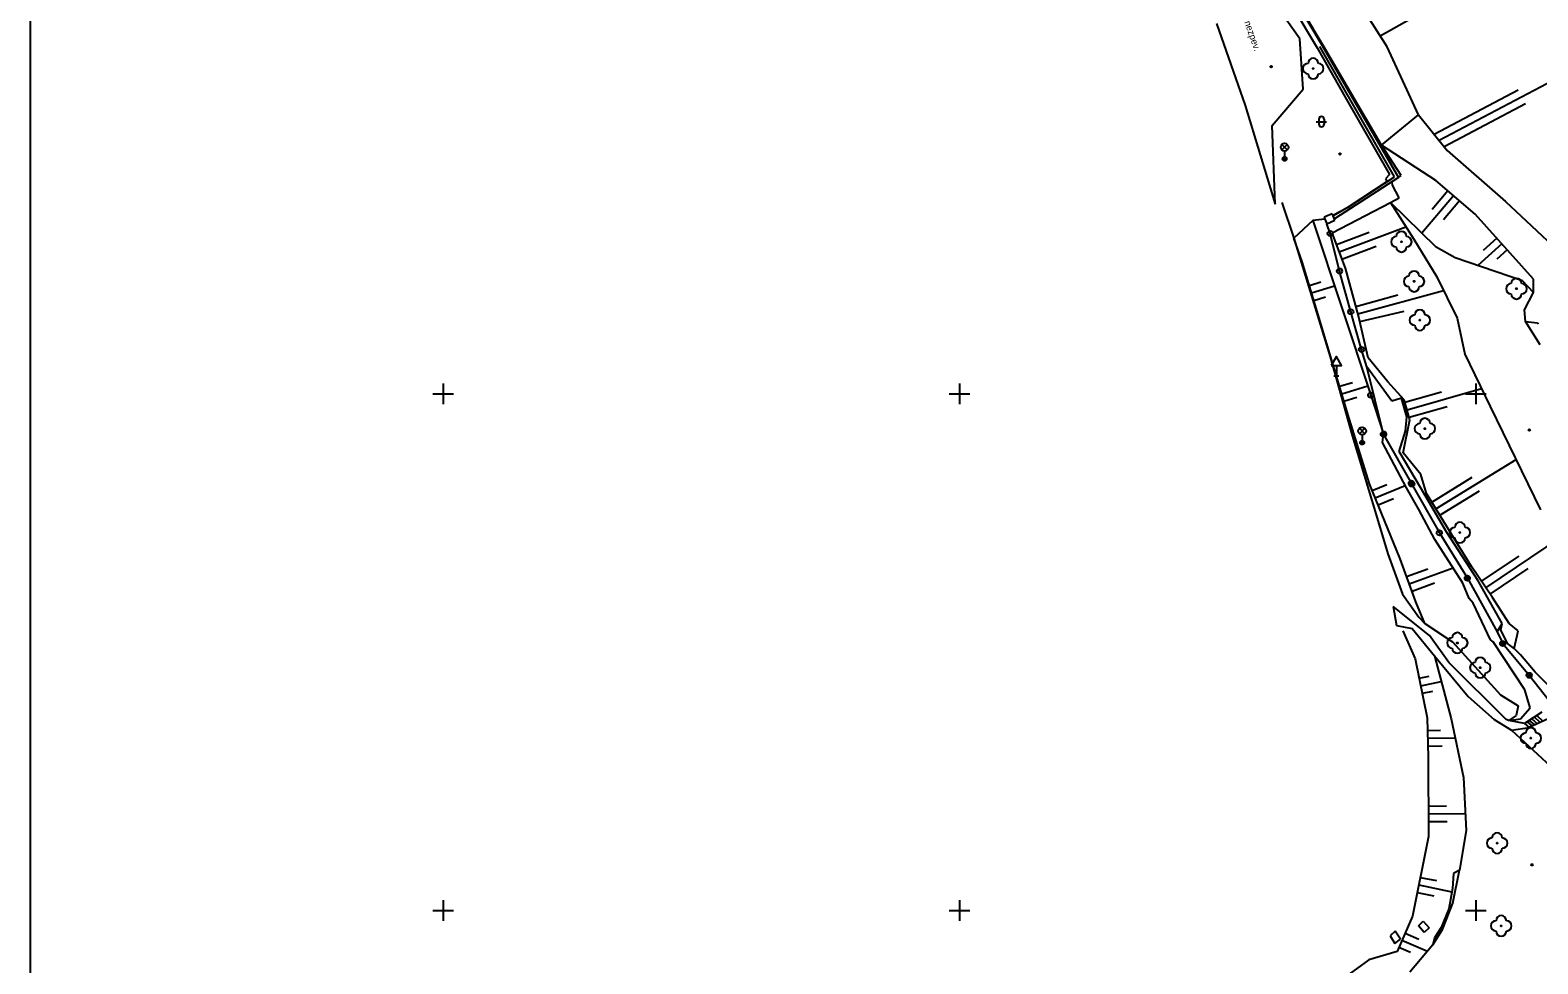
# Model space of a CAD drawing. Extents: x -639440 to -639026, y -1138850 to -1138262.
# Drawn here: x -639440 to -639294, y -1138555.2 to -1138464.8 of the extents above; entities that cross this region are included whole.
import ezdxf

# ---------------------------------------------------------------- set-up
doc = ezdxf.new("R2010")
doc.units = 0
for name, color, linetype in [('Vrstva 10', 7, 'Continuous'), ('Vrstva 11', 7, 'Continuous'), ('Vrstva 14', 7, 'Continuous'), ('Vrstva 15', 7, 'Continuous'), ('Vrstva 20', 7, 'Continuous'), ('Vrstva 22', 7, 'Continuous'), ('Vrstva 25', 7, 'Continuous'), ('Vrstva 33', 7, 'Continuous'), ('Vrstva 34', 7, 'Continuous'), ('Vrstva 36', 7, 'Continuous'), ('Vrstva 40', 7, 'Continuous'), ('Vrstva 60', 7, 'Continuous'), ('Vrstva 61', 7, 'Continuous'), ('Vrstva 7', 7, 'Continuous'), ('Vrstva 9', 7, 'Continuous')]:
    doc.layers.add(name, color=color, linetype=linetype)

msp = doc.modelspace()

# ---------------------------------------------------------------- linework, layer by layer
at = {"layer": 'Vrstva 10'}
for p, q in [((-639325.12, -1138464.14), (-639322.36, -1138472.06)), ((-639322.36, -1138472.06), (-639319.43, -1138481.64))]:
    msp.add_line(p, q, dxfattribs=at)
at = {"layer": 'Vrstva 11'}
for p, q in [((-639317.05, -1138465.63), (-639320.13, -1138461.24)), ((-639317.37, -1138462.09), (-639314.89, -1138466.26)), ((-639314.8, -1138466.25), (-639316.58, -1138463.31)), ((-639316.73, -1138470.5), (-639317.05, -1138465.63)), ((-639314.89, -1138466.26), (-639307.51, -1138479.04)), ((-639309.16, -1138475.92), (-639314.8, -1138466.25)), ((-639319.74, -1138474.01), (-639316.73, -1138470.5)), ((-639319.43, -1138481.64), (-639319.74, -1138474.01)), ((-639307.24, -1138478.85), (-639309.16, -1138475.92)), ((-639307.51, -1138479.04), (-639313.71, -1138483.05)), ((-639308.11, -1138479.48), (-639307.24, -1138478.85)), ((-639308.09, -1138479.79), (-639308.11, -1138479.48)), ((-639307.43, -1138481.02), (-639308.09, -1138479.79)), ((-639313.92, -1138484.4), (-639308.27, -1138481.46)), ((-639308.27, -1138481.46), (-639307.43, -1138481.02)), ((-639312.64, -1138487.82), (-639313.92, -1138484.4)), ((-639311.38, -1138492.43), (-639312.64, -1138487.82)), ((-639310.42, -1138496.5), (-639311.38, -1138492.43)), ((-639294.03, -1138493.13), (-639293.98, -1138493.25)), ((-639308.52, -1138498.84), (-639310.42, -1138496.5)), ((-639306.95, -1138500.56), (-639308.52, -1138498.84)), ((-639306.39, -1138502.52), (-639306.95, -1138500.56)), ((-639307.05, -1138505.69), (-639306.39, -1138502.52)), ((-639305.32, -1138507.81), (-639307.05, -1138505.69)), ((-639304.79, -1138509.65), (-639305.32, -1138507.81)), ((-639302.12, -1138514), (-639304.79, -1138509.65)), ((-639300.42, -1138516.71), (-639302.12, -1138514)), ((-639298.41, -1138519.7), (-639300.42, -1138516.71)), ((-639296.77, -1138522.21), (-639298.41, -1138519.7)), ((-639304.51, -1138523.4), (-639308.01, -1138520.58)), ((-639308.01, -1138520.58), (-639307.68, -1138522.42)), ((-639307.68, -1138522.42), (-639306.17, -1138522.72)), ((-639306.17, -1138522.72), (-639304.02, -1138525.35)), ((-639296.93, -1138524.15), (-639297.59, -1138522.83)), ((-639295.92, -1138522.92), (-639296.77, -1138522.21)), ((-639296.02, -1138523.37), (-639295.92, -1138522.92)), ((-639302.61, -1138526), (-639304.51, -1138523.4)), ((-639296.29, -1138524.64), (-639296.93, -1138524.15)), ((-639296.29, -1138524.64), (-639296.02, -1138523.37)), ((-639304.02, -1138525.35), (-639300.76, -1138529.29)), ((-639295.7, -1138525.25), (-639296.29, -1138524.64)), ((-639294.25, -1138526.93), (-639295.7, -1138525.25)), ((-639297.06, -1138531.52), (-639302.61, -1138526)), ((-639291.3, -1138529.94), (-639294.25, -1138526.93)), ((-639300.76, -1138529.29), (-639298.24, -1138531.51)), ((-639298.24, -1138531.51), (-639296.56, -1138532.54)), ((-639296.83, -1138531.6), (-639297.06, -1138531.52)), ((-639295.29, -1138531.92), (-639296.83, -1138531.6)), ((-639293.63, -1138530.81), (-639295.29, -1138531.92)), ((-639295.05, -1138531.76), (-639294.57, -1138532.17)), ((-639293, -1138531.44), (-639294.83, -1138532.29)), ((-639294.31, -1138532.05), (-639294.82, -1138531.6)), ((-639294.58, -1138531.44), (-639294.05, -1138531.93)), ((-639293.78, -1138531.8), (-639294.34, -1138531.29)), ((-639294.1, -1138531.13), (-639293.52, -1138531.68)), ((-639296.56, -1138532.54), (-639294.83, -1138532.29)), ((-639295.29, -1138531.92), (-639294.83, -1138532.29)), ((-639302.23, -1138549.3), (-639301.59, -1138546.12)), ((-639303.23, -1138551.86), (-639302.23, -1138549.3)), ((-639307.81, -1138552.02), (-639308.32, -1138552.47)), ((-639307.3, -1138552.78), (-639307.81, -1138552.02)), ((-639305.56, -1138551.51), (-639305.12, -1138551.05)), ((-639305.01, -1138552.15), (-639305.56, -1138551.51)), ((-639305.12, -1138551.05), (-639304.52, -1138551.69)), ((-639304.52, -1138551.69), (-639305.01, -1138552.15)), ((-639304.18, -1138553.34), (-639303.23, -1138551.86)), ((-639308.32, -1138552.47), (-639307.84, -1138553.2)), ((-639307.84, -1138553.2), (-639307.3, -1138552.78))]:
    msp.add_line(p, q, dxfattribs=at)
at = {"layer": 'Vrstva 14'}
for p, q in [((-639308.59, -1138466.4), (-639312.52, -1138460.23)), ((-639305.57, -1138472.99), (-639308.59, -1138466.4)), ((-639309.16, -1138475.92), (-639305.57, -1138472.99)), ((-639305.57, -1138472.99), (-639302.77, -1138476.43)), ((-639303.89, -1138479.35), (-639309.16, -1138475.92)), ((-639302.77, -1138476.43), (-639297.13, -1138481.38)), ((-639300.09, -1138482.58), (-639303.89, -1138479.35)), ((-639303.85, -1138485.78), (-639308.27, -1138481.46)), ((-639308.27, -1138481.46), (-639306.02, -1138485.03)), ((-639297.13, -1138481.38), (-639291.07, -1138487.06)), ((-639315.78, -1138483.2), (-639317.62, -1138484.91)), ((-639314.62, -1138483.07), (-639315.78, -1138483.2)), ((-639315.78, -1138483.2), (-639310.19, -1138500.12)), ((-639294.41, -1138488.89), (-639300.09, -1138482.58)), ((-639316.84, -1138487.2), (-639317.62, -1138484.91)), ((-639306.02, -1138485.03), (-639303.8, -1138488.65)), ((-639302.01, -1138486.83), (-639303.85, -1138485.78)), ((-639315.46, -1138491.7), (-639316.84, -1138487.2)), ((-639295.48, -1138489.05), (-639302.01, -1138486.83)), ((-639303.8, -1138488.65), (-639301.83, -1138492.65)), ((-639294.43, -1138490.17), (-639295.48, -1138489.05)), ((-639294.43, -1138490.17), (-639294.41, -1138488.89)), ((-639295.31, -1138491.87), (-639294.43, -1138490.17)), ((-639312.41, -1138501.95), (-639315.46, -1138491.7)), ((-639295.21, -1138492.98), (-639295.31, -1138491.87)), ((-639301.83, -1138492.65), (-639301.07, -1138496.16)), ((-639295.21, -1138492.98), (-639294.03, -1138493.13)), ((-639293.77, -1138495.26), (-639295.21, -1138492.98)), ((-639301.07, -1138496.16), (-639298.62, -1138501.22)), ((-639308.14, -1138500.71), (-639310.58, -1138497.36)), ((-639310.19, -1138500.12), (-639308.95, -1138503.88)), ((-639307.21, -1138500.41), (-639308.14, -1138500.71)), ((-639306.68, -1138502.2), (-639307.21, -1138500.41)), ((-639310.32, -1138508.71), (-639312.41, -1138501.95)), ((-639306.82, -1138503.59), (-639306.68, -1138502.2)), ((-639298.62, -1138501.22), (-639293.74, -1138511.22)), ((-639309.06, -1138504.69), (-639308.95, -1138503.92)), ((-639308.95, -1138503.88), (-639308.95, -1138503.92)), ((-639307.44, -1138505.57), (-639306.82, -1138503.59)), ((-639306.73, -1138509.1), (-639309.06, -1138504.69)), ((-639305.38, -1138509.06), (-639307.44, -1138505.57)), ((-639307.34, -1138515.95), (-639310.32, -1138508.71)), ((-639305.52, -1138511.19), (-639306.73, -1138509.1)), ((-639302.81, -1138513.41), (-639305.38, -1138509.06)), ((-639303.98, -1138514.08), (-639305.52, -1138511.19)), ((-639301.28, -1138518.33), (-639303.98, -1138514.08)), ((-639299.8, -1138518.09), (-639302.81, -1138513.41)), ((-639305.81, -1138520.14), (-639307.34, -1138515.95)), ((-639300.67, -1138519.79), (-639301.28, -1138518.33)), ((-639297.47, -1138522.23), (-639299.8, -1138518.09)), ((-639300.28, -1138520.27), (-639300.67, -1138519.79)), ((-639304.96, -1138522.23), (-639305.81, -1138520.14)), ((-639298.58, -1138523.82), (-639300.28, -1138520.27)), ((-639307.07, -1138522.94), (-639305.87, -1138525.66)), ((-639304.96, -1138522.23), (-639302.27, -1138524.01)), ((-639297.95, -1138523.04), (-639297.47, -1138522.23)), ((-639297.59, -1138522.83), (-639297.47, -1138522.23)), ((-639302.27, -1138524.01), (-639297.63, -1138529.12)), ((-639298.34, -1138524.01), (-639298.58, -1138523.82)), ((-639295.26, -1138528.66), (-639298.34, -1138524.01)), ((-639305.87, -1138525.66), (-639304.71, -1138531.35)), ((-639304.02, -1138525.35), (-639302.41, -1138531.46)), ((-639294.75, -1138530.39), (-639295.26, -1138528.66)), ((-639297.63, -1138529.12), (-639295.92, -1138530.19)), ((-639295.92, -1138530.19), (-639296.12, -1138531.13)), ((-639304.71, -1138531.35), (-639304.64, -1138535.15)), ((-639302.41, -1138531.46), (-639301.21, -1138537.14)), ((-639296.12, -1138531.13), (-639296.83, -1138531.6)), ((-639296.83, -1138531.6), (-639295.7, -1138531.45)), ((-639295.7, -1138531.45), (-639294.75, -1138530.39)), ((-639296.56, -1138532.54), (-639284.16, -1138544.03)), ((-639304.64, -1138535.15), (-639304.6, -1138542.85)), ((-639301.21, -1138537.14), (-639300.94, -1138542.27)), ((-639304.6, -1138542.85), (-639306.15, -1138550.57)), ((-639300.94, -1138542.27), (-639301.59, -1138546.12)), ((-639301.59, -1138546.12), (-639302.16, -1138546.44)), ((-639302.16, -1138546.44), (-639302.26, -1138547.87)), ((-639302.26, -1138547.87), (-639302.63, -1138549.84)), ((-639306.15, -1138550.57), (-639307.64, -1138553.98)), ((-639302.63, -1138549.84), (-639303.36, -1138551.64)), ((-639303.36, -1138551.64), (-639304, -1138552.66)), ((-639304.18, -1138553.34), (-639306.41, -1138555.98)), ((-639304, -1138552.66), (-639304.18, -1138553.34)), ((-639310.38, -1138554.79), (-639314.54, -1138557.83)), ((-639307.64, -1138553.98), (-639310.38, -1138554.79))]:
    msp.add_line(p, q, dxfattribs=at)
at = {"layer": 'Vrstva 15'}
for p, q in [((-639309.28, -1138465.32), (-639300.79, -1138460.55)), ((-639303.57, -1138475.44), (-639287.54, -1138467)), ((-639304.06, -1138474.85), (-639295.9, -1138470.56)), ((-639303.09, -1138476.04), (-639295.2, -1138471.89)), ((-639302.73, -1138480.33), (-639304.25, -1138482.13)), ((-639302.16, -1138480.82), (-639305.24, -1138484.44)), ((-639301.59, -1138481.31), (-639303.14, -1138483.13)), ((-639313.5, -1138485.53), (-639310.34, -1138484.35)), ((-639313.23, -1138486.23), (-639306.78, -1138483.82)), ((-639297.98, -1138484.92), (-639299.31, -1138486.11)), ((-639312.97, -1138486.94), (-639309.67, -1138485.7)), ((-639297.48, -1138485.48), (-639299.81, -1138487.58)), ((-639296.98, -1138486.04), (-639297.99, -1138486.94)), ((-639316.13, -1138489.5), (-639315.03, -1138489.16)), ((-639315.91, -1138490.22), (-639313.69, -1138489.54)), ((-639315.69, -1138490.94), (-639314.57, -1138490.59)), ((-639311.63, -1138491.53), (-639307.55, -1138490.42)), ((-639311.43, -1138492.25), (-639303.14, -1138489.99)), ((-639311.25, -1138492.98), (-639306.96, -1138491.97)), ((-639313.21, -1138499.26), (-639311.96, -1138498.89)), ((-639313, -1138499.98), (-639310.48, -1138499.23)), ((-639306.67, -1138501.53), (-639299.47, -1138499.47)), ((-639312.78, -1138500.7), (-639311.52, -1138500.32)), ((-639306.88, -1138500.81), (-639303.34, -1138499.8)), ((-639306.47, -1138502.25), (-639302.8, -1138501.21)), ((-639303.89, -1138511.11), (-639296.12, -1138506.34)), ((-639304.28, -1138510.47), (-639300.37, -1138508.07)), ((-639310.06, -1138509.35), (-639308.64, -1138508.77)), ((-639309.77, -1138510.05), (-639306.86, -1138508.85)), ((-639303.5, -1138511.75), (-639299.64, -1138509.39)), ((-639309.48, -1138510.74), (-639307.99, -1138510.12)), ((-639299.04, -1138518.76), (-639291.72, -1138513.84)), ((-639299.46, -1138518.14), (-639295.82, -1138515.69)), ((-639306.71, -1138517.68), (-639304.67, -1138516.94)), ((-639306.45, -1138518.39), (-639302.22, -1138516.84)), ((-639298.62, -1138519.38), (-639294.94, -1138516.91)), ((-639306.19, -1138519.09), (-639304, -1138518.29)), ((-639305.49, -1138527.51), (-639304.52, -1138527.32)), ((-639305.34, -1138528.25), (-639303.36, -1138527.84)), ((-639305.19, -1138528.98), (-639304.18, -1138528.78)), ((-639304.69, -1138532.59), (-639303.43, -1138532.56)), ((-639304.67, -1138533.34), (-639302.02, -1138533.29)), ((-639304.66, -1138534.09), (-639303.26, -1138534.06)), ((-639304.62, -1138539.9), (-639302.84, -1138539.89)), ((-639304.61, -1138540.65), (-639301.03, -1138540.63)), ((-639304.61, -1138541.4), (-639302.8, -1138541.39)), ((-639305.54, -1138547.54), (-639302.32, -1138548.19)), ((-639305.39, -1138546.81), (-639303.81, -1138547.12)), ((-639305.69, -1138548.28), (-639304.07, -1138548.6)), ((-639306.86, -1138552.19), (-639305.52, -1138552.77)), ((-639307.46, -1138553.56), (-639306.33, -1138554.06)), ((-639307.16, -1138552.88), (-639304.7, -1138553.95))]:
    msp.add_line(p, q, dxfattribs=at)
at = {"layer": 'Vrstva 20'}
for centre, radius in [((-639319.83, -1138468.31), 0.075), ((-639319.83, -1138468.31), 0.0204), ((-639313.17, -1138476.77), 0.075), ((-639313.17, -1138476.77), 0.0204), ((-639294.83, -1138503.49), 0.075), ((-639294.83, -1138503.49), 0.0204), ((-639294.58, -1138545.59), 0.075), ((-639294.58, -1138545.59), 0.0204)]:
    msp.add_circle(centre, radius, dxfattribs=at)
at = {"layer": 'Vrstva 22'}
for centre in [(-639315.76, -1138468.5), (-639307.22, -1138485.26), (-639305.99, -1138489.1), (-639296.08, -1138489.81), (-639305.43, -1138492.85), (-639304.94, -1138503.36), (-639301.55, -1138513.42), (-639301.8, -1138524.11), (-639299.58, -1138526.5), (-639294.68, -1138533.32), (-639297.95, -1138543.49), (-639297.55, -1138551.5)]:
    msp.add_circle(centre, 0.05, dxfattribs=at)
for centre, start, end in [((-639315.76, -1138468), 0, 180), ((-639316.26, -1138468.5), 90, 270), ((-639315.76, -1138469), 180, 0), ((-639315.26, -1138468.5), 270, 90), ((-639307.72, -1138485.26), 90, 270), ((-639307.22, -1138484.76), 0, 180), ((-639306.72, -1138485.26), 270, 90), ((-639307.22, -1138485.76), 180, 0), ((-639306.49, -1138489.1), 90, 270), ((-639305.99, -1138488.6), 0, 180), ((-639305.49, -1138489.1), 270, 90), ((-639296.58, -1138489.81), 90, 270), ((-639296.08, -1138489.31), 0, 180), ((-639295.58, -1138489.81), 270, 90), ((-639305.99, -1138489.6), 180, 0), ((-639296.08, -1138490.31), 180, 0), ((-639305.93, -1138492.85), 90, 270), ((-639305.43, -1138492.35), 0, 180), ((-639304.93, -1138492.85), 270, 90), ((-639305.43, -1138493.35), 180, 0), ((-639304.94, -1138502.86), 0, 180), ((-639305.44, -1138503.36), 90, 270), ((-639304.94, -1138503.86), 180, 0), ((-639304.44, -1138503.36), 270, 90), ((-639301.55, -1138512.92), 0, 180), ((-639302.05, -1138513.42), 90, 270), ((-639301.55, -1138513.92), 180, 0), ((-639301.05, -1138513.42), 270, 90), ((-639302.3, -1138524.11), 90, 270), ((-639301.8, -1138523.61), 0, 180), ((-639301.3, -1138524.11), 270, 90), ((-639301.8, -1138524.61), 180, 0), ((-639299.58, -1138526), 0, 180), ((-639300.08, -1138526.5), 90, 270), ((-639299.58, -1138527), 180, 0), ((-639299.08, -1138526.5), 270, 90), ((-639295.18, -1138533.32), 90, 270), ((-639294.68, -1138532.82), 0, 180), ((-639294.18, -1138533.32), 270, 90), ((-639294.68, -1138533.82), 180, 0), ((-639298.45, -1138543.49), 90, 270), ((-639297.95, -1138542.99), 0, 180), ((-639297.45, -1138543.49), 270, 90), ((-639297.95, -1138543.99), 180, 0), ((-639297.55, -1138551), 0, 180), ((-639298.05, -1138551.5), 90, 270), ((-639297.55, -1138552), 180, 0), ((-639297.05, -1138551.5), 270, 90)]:
    msp.add_arc(centre, 0.5, start, end, dxfattribs=at)
at = {"layer": 'Vrstva 25'}
for centre, radius in [((-639314.11, -1138484.47), 0.25), ((-639314.11, -1138484.47), 0.0303), ((-639313.21, -1138488.1), 0.25), ((-639313.21, -1138488.1), 0.0303), ((-639312.12, -1138492.04), 0.25), ((-639312.12, -1138492.04), 0.0303), ((-639311.08, -1138495.69), 0.25), ((-639311.08, -1138495.69), 0.0303), ((-639310.19, -1138500.12), 0.25), ((-639310.19, -1138500.12), 0.0303), ((-639308.95, -1138503.88), 0.25), ((-639308.95, -1138503.92), 0.25), ((-639308.95, -1138503.92), 0.2), ((-639308.95, -1138503.92), 0.15), ((-639308.95, -1138503.92), 0.1), ((-639308.95, -1138503.92), 0.05), ((-639308.95, -1138503.88), 0.0303), ((-639306.26, -1138508.64), 0.25), ((-639306.21, -1138508.72), 0.25), ((-639306.21, -1138508.72), 0.2), ((-639306.21, -1138508.72), 0.15), ((-639306.21, -1138508.72), 0.1), ((-639306.26, -1138508.64), 0.0303), ((-639306.21, -1138508.72), 0.05), ((-639303.54, -1138513.44), 0.25), ((-639303.54, -1138513.44), 0.0303), ((-639300.83, -1138517.84), 0.25), ((-639300.83, -1138517.84), 0.2), ((-639300.83, -1138517.84), 0.15), ((-639300.83, -1138517.84), 0.1), ((-639300.83, -1138517.84), 0.05), ((-639297.41, -1138524.17), 0.25), ((-639297.41, -1138524.17), 0.2), ((-639297.41, -1138524.17), 0.15), ((-639297.41, -1138524.17), 0.1), ((-639297.41, -1138524.17), 0.05), ((-639294.84, -1138527.24), 0.25), ((-639294.84, -1138527.24), 0.2), ((-639294.84, -1138527.24), 0.15), ((-639294.84, -1138527.24), 0.1), ((-639294.84, -1138527.24), 0.05)]:
    msp.add_circle(centre, radius, dxfattribs=at)
at = {"layer": 'Vrstva 33'}
for p, q in [((-639318.8, -1138476.38), (-639318.27, -1138475.85)), ((-639318.8, -1138475.85), (-639318.27, -1138476.38)), ((-639318.53, -1138476.49), (-639318.53, -1138477.24)), ((-639311.29, -1138503.85), (-639310.76, -1138503.32)), ((-639311.29, -1138503.32), (-639310.76, -1138503.85)), ((-639311.02, -1138503.96), (-639311.02, -1138504.71))]:
    msp.add_line(p, q, dxfattribs=at)
for centre, radius in [((-639318.53, -1138476.11), 0.375), ((-639318.53, -1138477.24), 0.2), ((-639318.53, -1138477.24), 0.145), ((-639318.53, -1138477.24), 0.0876), ((-639311.02, -1138503.58), 0.375), ((-639311.02, -1138504.71), 0.2), ((-639311.02, -1138504.71), 0.145), ((-639311.02, -1138504.71), 0.0876)]:
    msp.add_circle(centre, radius, dxfattribs=at)
at = {"layer": 'Vrstva 34'}
for p, q in [((-639313.51, -1138497.24), (-639313.51, -1138498.26)), ((-639313.76, -1138498.26), (-639313.26, -1138498.26))]:
    msp.add_line(p, q, dxfattribs=at)
msp.add_lwpolyline([(-639314.01, -1138497.24), (-639313.01, -1138497.24), (-639313.51, -1138496.38)], close=True, dxfattribs=at)
at = {"layer": 'Vrstva 36'}
for p, q in [((-639315.21, -1138473.39), (-639315.21, -1138473.89)), ((-639314.71, -1138473.39), (-639314.71, -1138473.89)), ((-639315.46, -1138473.64), (-639314.46, -1138473.64))]:
    msp.add_line(p, q, dxfattribs=at)
for centre, start, end in [((-639314.96, -1138473.39), 0, 180), ((-639314.96, -1138473.89), 180, 0)]:
    msp.add_arc(centre, 0.25, start, end, dxfattribs=at)
at = {"layer": 'Vrstva 60'}
msp.add_lwpolyline([(-639440, -1138261.5), (-639440, -1138850), (-639025.5, -1138850), (-639025.5, -1138261.5)], close=True, dxfattribs=at)
at = {"layer": 'Vrstva 61'}
for p, q in [((-639400, -1138499), (-639400, -1138501)), ((-639350, -1138499), (-639350, -1138501)), ((-639300, -1138499), (-639300, -1138501)), ((-639401, -1138500), (-639399, -1138500)), ((-639351, -1138500), (-639349, -1138500)), ((-639301, -1138500), (-639299, -1138500)), ((-639400, -1138549), (-639400, -1138551)), ((-639350, -1138549), (-639350, -1138551)), ((-639300, -1138549), (-639300, -1138551)), ((-639401, -1138550), (-639399, -1138550)), ((-639351, -1138550), (-639349, -1138550)), ((-639301, -1138550), (-639299, -1138550))]:
    msp.add_line(p, q, dxfattribs=at)
at = {"layer": 'Vrstva 7'}
for p, q in [((-639317.83, -1138462.38), (-639315.36, -1138466.5)), ((-639315.36, -1138466.5), (-639312.53, -1138471.48)), ((-639307.89, -1138478.99), (-639315.11, -1138466.37)), ((-639312.53, -1138471.48), (-639308.36, -1138478.76)), ((-639312.37, -1138481.92), (-639307.89, -1138478.99)), ((-639308.36, -1138478.76), (-639308.75, -1138479.16)), ((-639308.75, -1138479.16), (-639308.61, -1138479.44)), ((-639308.61, -1138479.44), (-639312.37, -1138481.92)), ((-639313.86, -1138482.69), (-639312.37, -1138481.92)), ((-639312.37, -1138481.92), (-639313.83, -1138482.76)), ((-639314.53, -1138482.82), (-639314.69, -1138482.89)), ((-639314.69, -1138482.89), (-639314.62, -1138483.07)), ((-639314.62, -1138483.07), (-639314.45, -1138483.52)), ((-639313.92, -1138482.56), (-639314.53, -1138482.82)), ((-639314.45, -1138483.52), (-639313.66, -1138483.18)), ((-639314.11, -1138484.47), (-639314.45, -1138483.52)), ((-639313.83, -1138482.76), (-639313.92, -1138482.56)), ((-639313.66, -1138483.18), (-639313.83, -1138482.76)), ((-639313.21, -1138488.1), (-639314.11, -1138484.47)), ((-639312.12, -1138492.04), (-639313.21, -1138488.1)), ((-639311.08, -1138495.69), (-639312.12, -1138492.04)), ((-639310.58, -1138497.36), (-639311.08, -1138495.69)), ((-639308.95, -1138503.88), (-639310.58, -1138497.36)), ((-639308.95, -1138503.92), (-639306.21, -1138508.72)), ((-639306.26, -1138508.64), (-639303.54, -1138513.44)), ((-639303.54, -1138513.44), (-639300.83, -1138517.84)), ((-639300.83, -1138517.84), (-639297.95, -1138523.04)), ((-639297.95, -1138523.04), (-639297.41, -1138524.17)), ((-639297.41, -1138524.17), (-639294.84, -1138527.24)), ((-639294.84, -1138527.24), (-639291.59, -1138531.37))]:
    msp.add_line(p, q, dxfattribs=at)
at = {"layer": 'Vrstva 9'}
for p, q in [((-639318.81, -1138481.46), (-639317.62, -1138484.91)), ((-639317.62, -1138484.91), (-639314.13, -1138496.42)), ((-639314.13, -1138496.42), (-639312, -1138504.02)), ((-639312, -1138504.02), (-639309.67, -1138511.69)), ((-639309.67, -1138511.69), (-639308.53, -1138515.48)), ((-639308.53, -1138515.48), (-639307.11, -1138519.38)), ((-639307.11, -1138519.38), (-639305.52, -1138521.61)), ((-639305.52, -1138521.61), (-639304.96, -1138522.23))]:
    msp.add_line(p, q, dxfattribs=at)

# ---------------------------------------------------------------- texts
at = {"layer": 'Vrstva 40'}
msp.add_text('nezpev.', height=0.65, rotation=289.3778, dxfattribs=at).set_placement((-639322.44, -1138464))

doc.saveas('drawing.dxf')
